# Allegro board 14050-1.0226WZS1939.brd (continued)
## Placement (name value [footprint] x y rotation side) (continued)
C1980  SC1KP50V2KX-1DLGP  [C402H22]  151.29 150.88 0 bottom
C1981  SC1KP50V2KX-1DLGP  [C402H22]  145.45 191.9 180 bottom
C1982  SCD1U16V2KX-3DLGP  [C402H22]  146.34 191.9 180 bottom
C3131  SC100P3KV8JN-4-GP  [C1808H87]  64.04 19.56 0 bottom
C3366  SCD1U16V2KX-3DLGP  [C402H22]  127.92 41.53 180 top
C3367  SC10U10V5KX-2DLGP  [C805H50]  134.27 51.31 0 bottom
C3368  SCD1U16V2KX-3DLGP  [C402H22]  138.33 32.46 270 top
C3369  SCD1U16V2KX-3DLGP  [C402H22]  138.33 36.01 270 top
C3370  SCD1U16V2KX-3DLGP  [C402H22]  138.33 34.24 270 top
C3371  SCD1U16V2KX-3DLGP  [C402H22]  138.33 33.35 270 top
C3372  SCD1U16V2KX-3DLGP  [C402H22]  138.33 35.13 270 top
C3373  SCD1U16V2KX-3DLGP  [C402H22]  138.33 36.9 270 top
C3374  SCD1U16V2KX-3DLGP  [C402H22]  138.33 38.68 270 top
C3375  SCD1U16V2KX-3DLGP  [C402H22]  138.33 37.79 270 top
C3376  SCD01U50V2KX-1DLGP  [C402H22]  136.93 29.59 180 top
C3377  SCD1U16V2KX-3DLGP  [C402H22]  128.8 29.6 0 top
C3378  SCD1U16V2KX-3DLGP  [C402H22]  129.69 41.54 180 top
C3379  SCD1U16V2KX-3DLGP  [C402H22]  136.68 41.54 180 top
C3380  SCD01U50V2KX-1DLGP  [C402H22]  133.88 29.6 0 top
C3381  SCD01U50V2KX-1DLGP  [C402H22]  135.8 41.48 0 top
C3382  SCD1U16V2KX-3DLGP  [C402H22]  135.8 41.48 0 bottom
C3383  SCD1U16V2KX-3DLGP  [C402H22]  128.81 41.53 180 top
C3452  SCD01U50V2KX-1DLGP  [C402H22]  49.82 17.78 180 top
C3453  SCD1U16V2KX-3DLGP  [C402H22]  39.02 12.83 0 bottom
C3454  SCD1U16V2KX-3DLGP  [C402H22]  38.51 20.07 180 top
C3455  SCD1U25V2KX-1-DL-GP  [C402H22]  36.69 32.03 0 top
C3456  SCD1U25V2KX-LL-GP  [C402H22]  39.15 34.92 180 top
C3457  SCD01U50V2KX-1DLGP  [C402H22]  40.95 35.86 270 top
C3458  SCD01U50V2KX-1DLGP  [C402H22]  40.8 38.1 270 top
C3459  SC10U25V5KX-DL-GP  [C805H58]  49.94 43.05 90 top
C3460  SC10U25V5KX-DL-GP  [C805H58]  49.94 45.09 90 top
C4101  SC1U10V2KX-1DLGP  [C402H22]  94.52 52.2 180 bottom
C4102  SC1U10V2KX-1DLGP  [C402H22]  107.48 55.63 180 top
C6701  SCD1U16V2KX-3DLGP  [C402H22]  81.92 68.83 180 top
C6702  SCD1U16V2KX-3DLGP  [C402H22]  81.92 70.76 0 top
C6703  SC10U6D3V3MX-GP  [C603H38]  75.09 69.62 270 top
C6704  SCD01U50V2KX-1DLGP  [C402H22]  99.09 119.63 180 top
C6705  SC10U10V5KX-2GP  [C805H54]  93.25 117.47 270 top
C6706  SC10U10V5KX-2DLGP  [C805H50]  96.93 117.47 90 top
C6707  SCD1U10V2KX-4GP  [C402H20]  99.09 123.7 0 top
C6708  SCD1U16V2KX-3DLGP  [C402H22]  93.38 114.05 270 top
C6709  SCD1U16V2KX-3DLGP  [C402H22]  96.93 119 90 top
C6710  SC10U6D3V3MX-DL-GP  [C603H36]  48.42 117.73 270 top
C6711  SCD1U16V2KX-3DLGP  [C402H22]  48.67 104.01 270 top
C6712  SCD22U10V2KX-2-GP  [C402H22]  160.43 209.68 180 bottom
C6714  SC10U6D3V3MX-DL-GP  [C603H36]  159.29 209.55 180 bottom
C6715  SC10U6D3V3MX-DL-GP  [C603H36]  159.29 215.39 0 bottom
C6716  SC1U10V2KX-1GP  [C402H22]  90.97 118.49 0 top
C6717  SCD1U16V2KX-3DLGP  [C402H22]  48.29 80.01 270 top
C6718  SCD1U25V3KX-DLGP  [C603H36]  65.79 46.13 270 top
C6719  SCD1U25V3KX-DLGP  [C603H36]  69.27 29.69 180 top
C6720  SCD1U25V3KX-DLGP  [C603H36]  36.61 52.45 90 bottom
C6721  SCD1U16V2KX-3DLGP  [C402H22]  128.81 27.18 180 top
C6722  SC100P50V2JN-3DLGP  [C402H22]  32.8 20.95 0 top
C6723  SCD1U10V2KX-4GP  [C402H20]  111.67 92.96 180 bottom
C6724  SCD01U25V2KX-3DLGP  [C402H22]  83.6 58.29 180 bottom
C6725  SCD1U10V2KX-4GP  [C402H20]  88.93 54.23 270 bottom
C6726  SC4D7P50V2CN-1-DL-GP  [C402H22]  93.53 36.96 0 top
C6727  SC4D7P50V2CN-1-DL-GP  [C402H22]  92.11 36.96 0 top
C6728  SC4D7P50V2CN-1-DL-GP  [C402H22]  94.39 36.96 0 top
C6729  SC4D7P50V2CN-1-DL-GP  [C402H22]  95.84 36.96 0 top
CONVT1  CLX-CON10-10-GP  [CI1410M1HRL-NH]  25 36.65 270 top
CPU1  CARRIZO-L-GP  [BGA968M2937H74]  83 165 0 top
D1  1SS355-4-GP  [SOD323AKH38]  14.26 218.69 180 top
D4  IP4223CZ6-1-GP  [SOT-6H44]  168.25 107.6 270 top
D7  BAT54A-12-GP  [SOT23-2D4-312H44]  105.57 92.2 180 top
D16  P6SMB27A-1-GP  [DO214AAAK-1121H97]  62.52 26.67 180 top
D19  BAV99GP-GP  [SOT23-2D4-312H48]  62.72 36.4 180 bottom
D20  BAT54A-12-GP  [SOT23-2D4-312H44]  60.23 146.18 180 top
D21  AZ2015-01H-GP  [SOD523AKH28]  164.37 88.06 0 bottom
D23  BAT54C-11-GP  [SOT23-2D4-312H44]  73.06 49.07 90 top
D24  IP4223CZ6-1-GP  [SOT-6H44]  93.97 29.97 180 top
D31  1SS355-4-GP  [SOD323AKH38]  131.61 25.91 270 top
D32  BX310F-R1-00000-GP  [D4724AKH44]  37.75 41.58 270 top
D33  CH551H-30PT-GP  [SOD80CH36]  73.31 46.15 270 top
D34  BAT54A-12-GP  [SOT23-2D4-312H44]  103.67 105.54 0 top
DCIN1  DC-JACK345-GP  [2DC3115-000111F]  53.25 25.53 270 top
DCIN2  ACES-CONN14G-GP  [88314-077N]  55.64 33.67 180 top
DIMM1  DDR3-204P-262-GP-U  [AS0A621-J4R6-7H-U]  135.3 158.9 90 top
DIMM2  DDR3-204P-142-GP-U  [AS0A626-J8R6-7H]  150.5 158.9 90 top
F1  POLYSW-1D5A6V-12-GP  [POLYSW-2114H30]  160.31 194.56 180 bottom
F2  POLYSW-2A6V-7-GP  [POLYSW-2114H30]  39.53 107.44 270 bottom
F3  POLYSW-1D5A6V-12-GP  [POLYSW-2114H30]  161.75 190.53 90 bottom
F5  POLYSW-2A6V-7-GP  [POLYSW-2114H30]  6.13 210.44 0 bottom
F6  POLYSW-1D5A6V-12-GP  [POLYSW-2114H30]  161.7 142.75 0 top
F12  POLYSW-2A6V-7-GP  [POLYSW-2114H30]  105.82 18.67 180 top
F13  POLYSW-1D5A6V-12-GP  [POLYSW-2114H30]  107.09 32.77 270 top
F14  POLYSW-2A6V-7-GP  [POLYSW-2114H30]  169.07 124.71 90 top
F15  POLYSW-1D5A6V-12-GP  [POLYSW-2114H30]  24.29 6.22 270 bottom
F16  FUSE-3A32V-26-GP  [FUSE-1608H22]  50.58 49.07 270 top
FANC3  FOX-CON4-30-GP  [HF1804H]  14 211 270 top
G5  COPPER-CLOSE-GP-U  [CON2C-U]  141.77 36.83 180 top
GPU1  SUN-S3-XT-GP  [BGA631M23H82]  83 100 90 top
H1  HOLE237R158-GP  [HOLE237R158]  94.38 192.31 180 top
H2  HOLE237R158-GP  [HOLE237R158]  62.39 165.12 180 top
H3  HOLE237R158-GP  [HOLE237R158]  94.38 137.93 180 top
H4  HOLE237R158-GP  [HOLE237R158]  69 123.75 180 top
H5  HOLE237R158-GP  [HOLE237R158]  94.39 76.25 180 top
H6  GEN8D5X8R5X4D5-8-F-A-GP  [GEN8D5X8R5X4D5-8-F-A]  165 225 270 top
H7  GEN315R138-8-F-A-1-GP  [GEN315R138-8-F-A-1]  5 160 180 top
H9  GEN8D5X8R5X4D5-8-F-A-GP  [GEN8D5X8R5X4D5-8-F-A]  25 49.15 180 top
H10  GEN315R178-8-F-A-3-GP  [GEN315R178-8-F-A-1]  165 20 180 top
H11  GEN315R138-8-F-A-1-GP  [GEN315R138-8-F-A-1]  172.5 64.43 180 top
HDD1  SKT-SATA7P-184-GP-U  [15-02070-5A61-A]  12 142 270 top
HDMI1  SKT-HDMI22-12-GP  [SKT-HDMI22-150077]  113.99 37.03 270 top
HDMI2  ARG-CON20-GP  [LVDFH-02004-TP00]  118.69 37.07 270 top
HDT1  SMC-CONN20A-1-GP  [ASP-137098-05]  94.78 213.74 90 top
HS6  STF256R109H99-GP  [STF256R109H99]  144.25 214 180 top
L1  HCB2012KF-600T30-GP  [L20125H42]  35.97 107.44 270 bottom
L2  IND-2D2UH-250-GP-U  [L3030-2709H41]  31.83 104.65 0 bottom
L4  FILTER-4P-123-GP  [L125100-4P-1H36]  165.64 117.98 180 top
L5  FILTER-4P-123-GP  [L125100-4P-1H36]  165.64 115.7 180 top
L10  MHC1608S221NBP-GP  [L603H38]  153.2 37.08 90 top
L15  BLM15BD102SN1D-GP  [L402H22]  55.48 35.25 180 bottom
L16  HCB1608KF-800T30-GP  [L603H38]  39.99 105.71 270 bottom
L17  HCB1608KF-800T30-GP  [L603H38]  32.72 78.26 270 bottom
L19  HCB1608KF-800T30-GP  [L603H38]  165.64 88.27 180 bottom
L20  MCB1005S121FBP-GP  [L402H24]  82.58 38.1 180 top
L21  MCB1005S121FBP-GP  [L402H24]  158.86 74.85 0 bottom
L31  HCB2012KF-601T20-GP  [L20125H42]  142.53 20.83 0 top
L32  HCB2012KF-601T20-GP  [L20125H42]  144.69 20.83 0 top
L33  HCB2012KF-601T20-GP  [L20125H42]  150.15 20.83 0 top
L34  HCB2012KF-601T20-GP  [L20125H42]  147.99 20.83 0 top
L46  -  [0R0805-PAD]  107.09 34.92 270 top
L47  MCB1005S121FBP-GP  [L402H24]  96.3 99.57 180 bottom
L48  MCB1005S121FBP-GP  [L402H24]  93.4 105.14 90 bottom
L49  MCB1005S121FBP-GP  [L402H24]  74.61 81.89 180 top
L50  MCB1005S121FBP-GP  [L402H24]  79.43 87.61 90 bottom
L51  MCB1005S121FBP-GP  [L402H24]  73.34 81.89 180 top
L52  MHC1608S221NBP-GP  [L603H38]  92 94.21 0 bottom
L53  MHC1608S221NBP-GP  [L603H38]  89.08 91.04 270 bottom
L54  MCB1005S121FBP-GP  [L402H24]  157.51 84.71 270 top
L55  FCM1608KF-2-GP-U  [L1608-UH38]  107.6 19.05 180 top
L56  FILTER-4P-123-GP  [L125100-4P-1H36]  165.64 96.52 180 top
L57  FILTER-4P-123-GP  [L125100-4P-1H36]  165.64 94.23 180 top
L60  MHC1608S181NBP-GP  [L603H38]  141.77 39.75 90 top
L61  IND-33UH-83-GP  [L8080-6522-1H166]  43.01 47.8 270 top
L62  MCB1005S121FBP-GP  [L402H24]  84.74 37.21 180 top
L4101  BLM15HG102SN1D-GP  [L402H22]  106.08 54.86 180 top
L4102  FILTER-4P-123-GP  [L125100-4P-1H36]  18.83 140.84 0 top
L4103  FILTER-4P-123-GP  [L125100-4P-1H36]  18.83 143 0 top
LED2  LED-O-23-GP  [LED1608AKH30]  95.16 7.24 180 top
LED3  LED-O-23-GP  [LED1608AKH30]  168.05 128.91 90 top
LOUT1  AUDIO-JK419-GP  [JAC331-0140A8B-9H]  76.93 37.66 90 top
LPC1  FOX-CONN14A-S1-GP  [HL5507F]  120.28 55.09 0 top
LVDS1  ACES-CON30-21-GP  [50524-0300N-001]  36.8 95 270 top
MEM1  H5TQ1G63DFR-11C-1-GP  [BGA96D075130H48]  55.61 111.68 0 top
MEM2  H5TQ1G63DFR-11C-1-GP  [BGA96D075130H48]  55.61 91.62 180 top
MEM3  H5TQ1G63DFR-11C-1-GP  [BGA96D075130H48]  55.61 111.68 180 bottom
MEM4  H5TQ1G63DFR-11C-1-GP  [BGA96D075130H48]  55.61 91.62 0 bottom
MEMCD1  SKT-SDCARD-52-GP  [156-5101902601]  174.65 144.79 90 top
NGFF1  SKT-MINI67P-3-GP-U1  [2199230-7]  116 214 270 top
NOREF  -  []  -10 0 0 top
NOREF#2  -  [unnamed#2]  6.64 9.4 0 top
NOREF#3  *  [unnamed#2]  62.77 66.55 0 top
NOREF#4  *  [unnamed#2]  72.55 202.69 0 top
NOREF#5  -  []  152.81 98.04 0 top
NOREF#6  *  [unnamed#2]  171.63 8.45 0 top
NOREF#7  *  [unnamed#2]  7.78 219.33 0 top
NOREF#8  -  []  -10 0 0 top
NOREF#9  -  []  105.19 194.31 0 top
NOREF#10  -  []  -10 0 0 top
NOREF#11  -  [unnamed#2]  178.22 223.03 0 top
NOREF#12  *  [unnamed#2]  157.46 223.44 0 top
NOREF#13  -  []  -10 0 0 top
NOREF#14  -  []  133.89 208.03 0 top
NOREF#15  -  [unnamed#2]  6.64 225.3 0 top
NOREF#16  -  []  0 103.25 0 top
NOREF#17  *  [unnamed#2]  178.33 217.98 0 top
NOREF#18  -  [unnamed#2]  184.44 225.3 0 top
NOREF#19  -  []  113.73 178.94 0 top
NOREF#20  *  [unnamed#2]  166.66 27.56 0 top
NOREF#21  -  [unnamed#2]  171.63 4.95 0 top
NOREF#22  -  []  -310 0 0 top
NOREF#23  -  [unnamed#2]  11.57 4.95 0 top
NOREF#24  -  [unnamed#2]  149 223.77 0 top
NOREF#25  *  [unnamed#2]  101.76 136.14 0 top
NOREF#26  *  [unnamed#2]  40.67 23.11 0 top
NOREF#27  *  [unnamed#2]  5.05 6.01 0 top
NOREF#28  *  [unnamed#2]  171.63 8.45 180 bottom
NOREF#29  -  []  178.7 28.65 90 bottom
NOREF#30  *  [unnamed#2]  49.56 123.7 180 bottom
NOREF#31  *  [unnamed#2]  40.17 24.64 180 bottom
NOREF#32  *  [unnamed#2]  157.46 223.44 180 bottom
NOREF#33  *  [unnamed#2]  45.37 223.77 180 bottom
NOREF#34  -  []  120.05 156.34 90 bottom
NOREF#35  *  [unnamed#2]  178.33 217.98 180 bottom
NOREF#36  *  [unnamed#2]  5.05 6.01 180 bottom
ODD1  SKT-SATA7P-184-GP-U  [15-02070-5A61-A]  8.4 177 270 top
PC1  SC1U10V2KX-1DLGP  [C402H22]  124.87 208.41 90 bottom
PC4  SC22P50V2JN-4DLGP  [C402H22]  121.95 71.09 90 bottom
PC5  SCD22U25V3KX-GP  [C603H40]  122.31 72.87 180 bottom
PC6  SC150P50V2JN-3DLGP  [C402H22]  119.54 65.02 0 top
PC7  SC1KP50V2KX-1DLGP  [C402H22]  119.03 66.42 90 top
PC8  SC33P50V2JN-3DLGP  [C402H22]  120.94 66.42 90 top
PC9  SCD01U50V2KX-1GP  [C402H22]  120.18 72.52 0 bottom
PC11  SC390P50V2KX-1-GP  [C402H22]  128.81 71.25 180 top
PC12  SC2D2U10V3KX-1DLGP-U  [C603H36]  111.79 71.5 270 top
PC13  SC330P50V2KX-3-DL-GP  [C402H22]  126.91 73.28 180 top
PC14  SCD01U50V2KX-1GP  [C402H22]  127.54 74.93 90 top
PC15  SCD033U25V2KX-1-GP  [C402H22]  130.46 75.31 180 bottom
PC16  SCD22U25V3KX-DL-GP  [C603H36]  129.19 75.69 180 bottom
PC17  SC1U16V3KX-4DLGP  [C603H36]  119.67 80.64 180 top
PC18  SC1U16V3KX-4DLGP  [C603H36]  118.4 80.64 180 top
PC19  SCD22U25V3KX-DL-GP  [C603H36]  122.33 80.64 180 top
PC20  SCD1U50V3KX-DL-GP  [C603H35]  124.37 71.88 270 bottom
PC24  SC10U25V6KX-4DL-GP  [C1206H71]  120.94 87.25 90 bottom
PC34  SCD1U10V2KX-5GP  [C402H22]  101.25 64.64 90 bottom
PC48  SCD1U10V2KX-5GP  [C402H22]  17.43 157.35 270 bottom
PC49  SC1U16V3KX-4DLGP  [C603H36]  164.5 207.9 90 top
PC50  SC10U6D3V5KX-4DLGP-U  [C805H58]  154.21 207.52 270 top
PC51  SCD1U50V3KX-DL-GP  [C603H35]  152.69 205.87 90 top
PC52  SC10U6D3V5KX-4DLGP-U  [C805H58]  158.91 207.14 270 top
PC56  SC330P50V2KX-3-DL-GP  [C402H22]  123.86 72.9 90 bottom
PC57  SC1KP50V2KX-1DLGP  [C402H22]  123.86 73.79 270 bottom
PC58  SC1U16V3KX-4DLGP  [C603H36]  123.1 75.56 90 bottom
PC59  SCD1U16V3KX-3GP  [C603H36]  127.92 77.22 270 top
PC60  SCD22U25V3KX-DL-GP  [C603H36]  123.1 76.83 90 bottom
PC61  SC10U25V6KX-4DL-GP  [C1206H71]  120.94 89.41 270 top
PC62  SCD1U50V3KX-DL-GP  [C603H35]  120.94 91.19 270 top
PC63  SC10U25V6KX-4DL-GP  [C1206H71]  120.94 87.12 270 top
PC64  SC10U25V6KX-4DL-GP  [C1206H71]  120.94 89.53 90 bottom
PC65  SC1500P50V3KX-DLGP  [C603H36]  121.32 94.49 0 top
PC68  SC27P50V2JN-2DLGP  [C402H22]  66.2 80.77 90 top
PC73  SCD01U50V2KX-1DLGP  [C402H22]  86.01 94.36 270 bottom
PC96  SCD1U16V2KX-3DLGP  [C402H22]  105.95 6.99 0 top
PC126  SC22P50V2JN-4GP  [C402H22]  157.26 194.31 90 top
PC140  SC1U10V2KX-1DLGP  [C402H22]  39.66 8 0 bottom
PC151  SCD1U16V2KX-3DLGP  [C402H22]  72.42 78.36 90 top
PC2127  SC470P50V2KX-3DLGP  [C402H22]  152.81 17.02 270 top
PC4301  SC10P50V2JN-4DLGP  [C402H22]  35.21 64.39 90 top
PC4302  SCD1U50V3KX-DL-GP  [C603H35]  36.48 71.63 180 top
PC4303  SC2200P50V2KX-2DLGP  [C402H22]  36.48 71.5 0 bottom
PC4304  SC470P50V2KX-3DLGP  [C402H22]  35.21 61.34 90 top
PC4305  SC10P50V2JN-4DLGP  [C402H22]  35.21 65.28 90 top
PC4401  SC10U25V5KX-DL-GP  [C805H58]  34.86 71.27 0 bottom
PC4402  SCD1U50V3KX-DL-GP  [C603H35]  57.69 61.34 270 bottom
PC4403  SCD1U50V3KX-DL-GP  [C603H35]  59.09 62.61 270 bottom
PC4404  SCD1U50V3KX-DL-GP  [C603H35]  56.29 62.61 90 bottom
PC4405  SCD1U25V2KX-1-DL-GP  [C402H22]  42.63 54.79 90 top
PC4406  SC10U25V5KX-DL-GP  [C805H58]  43.21 53.34 270 bottom
PC4407  SC10U25V5KX-DL-GP  [C805H58]  43.21 53.34 90 top
PC4408  SC1U25V5KX-3-GP  [C805H58]  55.53 58.93 90 bottom
PC4426  SC1U25V3KX-1-GP  [C603H36]  73.06 53.72 90 bottom
PC4601  SC1KP50V2KX-1DLGP  [C402H22]  24.29 222.63 270 bottom
PC4602  SC1U25V3KX-1-DLGP  [C603H36]  32.01 220.47 0 top
PC4603  SC3300P50V2KX-1DLGP  [C402H22]  22.64 217.17 180 bottom
PC4605  SC1KP50V2KX-1DLGP  [C402H22]  34.96 224.03 0 bottom
PC4606  SC1KP50V2KX-1DLGP  [C402H22]  27.34 216.92 90 top
PC4607  SCD1U16V2KX-3DLGP  [C402H22]  26.83 224.03 180 bottom
PC4608  SC2D2U10V3KX-1DLGP-U  [C603H36]  31.4 215.52 180 top
PC4609  SCD01U50V2KX-1DLGP  [C402H22]  27.34 217.81 270 top
PC4610  SC330P50V2KX-3-DL-GP  [C402H22]  38.51 221.62 90 bottom
PC4611  SC2200P50V2KX-2DLGP  [C402H22]  38.51 219.58 90 bottom
PC4612  SC10P50V2JN-4DLGP  [C402H22]  36.99 220.09 180 bottom
PC4613  SC330P50V2KX-3-DL-GP  [C402H22]  37.5 215.52 90 bottom
PC4614  SCD01U50V2KX-1DLGP  [C402H22]  33.05 220.73 0 top
PC4615  SC680P50V2KX-2DLGP  [C402H22]  23.15 214.63 90 bottom
PC4616  SCD01U50V2KX-1DLGP  [C402H22]  33.05 218.69 270 top
PC4617  SC680P50V2KX-2DLGP  [C402H22]  37.5 214.63 270 bottom
PC4618  SC1KP50V2KX-1DLGP  [C402H22]  23.15 213.74 270 bottom
PC4619  SCD1U16V2KX-3DLGP  [C402H22]  35.97 220.73 180 top
PC4621  SC330P50V2KX-3-DL-GP  [C402H22]  21.75 221.11 180 bottom
PC4622  SC1KP50V2KX-1DLGP  [C402H22]  33.05 216.03 270 top
PC4623  SCD047U16V2KX-1-DL-GP  [C402H22]  37.5 214.63 90 top
PC4624  SC3300P50V2KX-1DLGP  [C402H22]  38.01 218.06 180 bottom
PC4626  SC2200P50V2KX-2DLGP  [C402H22]  22.26 218.57 270 bottom
PC4627  SC10P50V2JN-4DLGP  [C402H22]  23.66 219.07 180 bottom
PC4628  SCD047U16V2KX-1-DL-GP  [C402H22]  23.15 213.74 90 top
PC4701  SC10U25V6KX-4DL-GP  [C1206H71]  41.56 199.01 90 bottom
PC4702  SC10U25V6KX-4DL-GP  [C1206H71]  41.56 201.29 270 top
PC4703  SCD1U50V3KX-DL-GP  [C603H35]  41.44 199.52 270 top
PC4704  SCD22U25V3KX-DL-GP  [C603H36]  32.93 209.42 0 bottom
PC4705  SC10U25V6KX-4DL-GP  [C1206H71]  41.56 201.29 90 bottom
PC4706  SC1KP50V2KX-1DLGP  [C402H22]  42.45 195.2 180 top
PC4707  SC10U25V6KX-4DL-GP  [C1206H71]  27.85 201.19 270 bottom
PC4708  SC10U25V6KX-4DL-GP  [C1206H71]  27.85 201.17 90 top
PC4709  SCD1U50V3KX-DL-GP  [C603H35]  27.85 199.39 90 top
PC4710  SCD22U25V3KX-DL-GP  [C603H36]  28.74 209.42 0 bottom
PC4711  SC10U25V6KX-4DL-GP  [C1206H71]  27.85 199.01 270 bottom
PC4712  SC1KP50V2KX-1DLGP  [C402H22]  27.08 195.2 180 top
PC4713  SCD1U50V3KX-DL-GP  [C603H35]  29.75 164.59 90 top
PC4801  SC10U25V6KX-4DL-GP  [C1206H71]  26.07 157.86 0 top
PC4802  SCD1U16V2KX-3DLGP  [C402H22]  40.67 152.02 270 top
PC4803  SC1U10V2KX-1DLGP  [C402H22]  23.07 155.68 90 top
PC4804  SC1KP50V2KX-1DLGP  [C402H22]  17.43 156.46 270 bottom
PC4805  SC18P50V2JN-1DLGP  [C402H22]  13.62 154.18 180 top
PC4806  SCD1U50V3KX-DL-GP  [C603H35]  24.29 158.12 180 top
PC4807  SC1KP50V2KX-1DLGP  [C402H22]  33.18 156.84 270 top
PC4808  SC10U25V6KX-4DL-GP  [C1206H71]  26.07 157.86 180 bottom
PC4901  SCD01U50V2KX-1DLGP  [C402H22]  123.22 8.97 90 bottom
PC4902  SC10U25V6KX-4DL-GP  [C1206H71]  121.11 7.11 0 bottom
PC4903  SCD1U50V3KX-DL-GP  [C603H35]  115.6 10.16 180 top
PC4904  SC10U25V6KX-4DL-GP  [C1206H71]  120.48 23.24 180 bottom
PC4905  SCD01U50V2KX-1DLGP  [C402H22]  123.3 21.11 90 bottom
PC4906  SC1U10V2KX-1DLGP  [C402H22]  114.84 13.97 90 top
PC4907  SCD1U50V3KX-DL-GP  [C603H35]  112.05 6.22 0 top
PC4908  SCD1U50V3KX-DL-GP  [C603H35]  112.56 17.14 0 top
PC4909  SC1U10V2KX-1DLGP  [C402H22]  132.62 5.97 0 top
PC4910  SC1U10V2KX-1DLGP  [C402H22]  132.62 22.99 180 top
PC4911  SC22P50V2JN-4DLGP  [C402H22]  106.97 10.03 0 top
PC4912  SC1U16V3KX-4DLGP  [C603H36]  106.08 15.75 270 top
PC4913  SC22P50V2JN-4DLGP  [C402H22]  106.97 14.1 0 top
PC4914  SC4D7U6D3V3KX-DLGP  [C603H36]  115.22 14.99 270 top
PC4915  SC1500P50V3KX-DLGP  [C603H36]  122.92 20.09 90 bottom
PC4916  SC1500P50V3KX-DLGP  [C603H36]  122.84 10.01 90 bottom
PC4917  SC18P50V2JN-1DLGP  [C402H22]  106.46 14.1 90 bottom
PC4918  SC18P50V2JN-1DLGP  [C402H22]  106.46 10.03 90 bottom
PC5001  SC10U10V5KX-2DLGP  [C805H50]  136.05 80.77 270 top
PC5003  SC1KP50V2KX-1DLGP  [C402H22]  147.1 80.39 270 top
PC5009  SC1U10V2KX-1DLGP  [C402H22]  146.46 76.96 90 top
PC5010  SCD1U50V3KX-DL-GP  [C603H35]  144.31 83.57 0 top
PC5011  SC10U10V5KX-2DLGP  [C805H50]  137.32 83.95 180 top
PC5012  SC1U16V3KX-4DLGP  [C603H36]  143.29 104.01 0 top
PC5013  SC18P50V2JN-1DLGP  [C402H22]  139.99 74.04 90 top
PC5014  SCD033U25V3KX-DL-GP  [C603H36]  136.43 75.11 270 top
PC5016  SC10U10V5KX-2DLGP  [C805H50]  135.29 83.95 180 top
PC5017  SC1500P50V3KX-DLGP  [C603H36]  141.38 93.27 180 bottom
PC5018  SC1U10V2KX-1DLGP  [C402H22]  146.46 76.07 90 top
PC5019  SCD1U50V3KX-DL-GP  [C603H35]  138.84 92.58 270 bottom
PC5020  SC10U25V6KX-4DL-GP  [C1206H71]  138.84 88.52 270 bottom
PC5021  SC10U25V6KX-4DL-GP  [C1206H71]  138.84 90.81 270 bottom
PC5022  SC10U25V6KX-4DL-GP  [C1206H71]  138.84 88.52 90 top
PC5202  SC1500P50V3KX-DLGP  [C603H36]  107.22 66.8 270 bottom
PC5203  SC22P50V2JN-4DLGP  [C402H22]  101.25 61.59 90 top
PC5204  SC1U10V2KX-1DLGP  [C402H22]  101.25 64.64 270 top
PC5205  SC22U6D3V3MX-1-DL-GP  [C603H40]  103.03 77.34 180 top
PC5209  SC10U25V6KX-4DL-GP  [C1206H71]  106.97 58.55 90 top
PC5210  SC22U6D3V3MX-1-DL-GP  [C603H40]  104.3 77.34 180 top
PC5211  SC22U6D3V3MX-1-DL-GP  [C603H40]  105.57 77.34 180 top
PC5212  SC22U6D3V3MX-1-DL-GP  [C603H40]  101.76 77.34 180 top
PC5213  SCD1U16V2KX-3DLGP  [C402H22]  100.62 77.34 180 top
PC5214  SC10U25V6KX-4DL-GP  [C1206H71]  106.97 60.83 90 top
PC5217  SCD1U25V2KX-1-DL-GP  [C402H22]  101.25 66.67 90 top
PC5232  SCD01U50V2KX-1DLGP  [C402H22]  65.44 57.53 270 bottom
PC5233  SC1U10V2KX-1DLGP  [C402H22]  55.63 53.34 0 bottom
PC5234  SCD1U50V3KX-DL-GP  [C603H35]  55.91 57.23 270 bottom
PC5235  SC1KP50V2KX-1DLGP  [C402H22]  44.94 70.15 180 top
PC5236  SCD1U50V3KX-DL-GP  [C603H35]  60.99 49.78 270 bottom
PC5237  SC470P50V2KX-3DLGP  [C402H22]  58.86 51.99 180 bottom
PC5238  SCD1U25V2KX-1-DL-GP  [C402H22]  62.77 49.28 180 bottom
PC5239  SC220P50V2KX-3DLGP  [C402H22]  65.44 56.52 270 bottom
PC5240  SC10U25V5KX-DL-GP  [C805H58]  34.86 71.27 180 top
PC5241  SC10U25V5KX-DL-GP  [C805H58]  38.13 64.14 0 top
PC5242  SCD1U50V3KX-DL-GP  [C603H35]  39.78 64.26 0 top
PC5243  SC1U16V3KX-4DLGP  [C603H36]  18.96 147.83 270 top
PC5244  SC100P50V2JN-3DLGP  [C402H22]  31.28 143.26 0 top
PC5245  SCD1U10V2KX-5GP  [C402H22]  22 138.68 0 top
PC5246  SC1U16V3KX-4DLGP  [C603H36]  32.42 146.81 180 top
PC5247  SC10U10V5KX-2DLGP  [C805H50]  24.93 148.72 180 top
PC5248  SC10U10V5KX-2DLGP  [C805H50]  30.77 146.69 180 top
PC5401  SC10U25V6KX-4DL-GP  [C1206H71]  49.31 214.88 90 top
PC5402  SC10U25V6KX-4DL-GP  [C1206H71]  49.31 217.42 90 top
PC5403  SCD1U50V3KX-DL-GP  [C603H35]  49.94 216.03 270 bottom
PC5404  SC10U25V6KX-4DL-GP  [C1206H71]  42.22 212.57 270 top
PC5405  SC1KP50V2KX-1DLGP  [C402H22]  52.99 221.11 0 bottom
PC5411  SCD22U25V3KX-DL-GP  [C603H36]  71.66 213.74 270 bottom
PC5413  SC1KP50V2KX-1DLGP  [C402H22]  77.5 218.69 0 top
PC5414  SC1KP50V2KX-1DLGP  [C402H22]  75.09 222.88 180 bottom
PC5415  SC330P50V2KX-3-DL-GP  [C402H22]  82.84 223.9 180 bottom
PC5416  SC10P50V2JN-4DLGP  [C402H22]  81.95 222.88 180 bottom
PC5417  SC2200P50V2KX-2DLGP  [C402H22]  81.06 222.88 180 bottom
PC5418  SC1KP50V2KX-1DLGP  [C402H22]  84.74 219.2 180 bottom
PC5419  SC3300P50V2KX-1DLGP  [C402H22]  79.66 222.38 90 bottom
PC5420  SC1U25V3KX-1-DLGP  [C603H36]  85.63 214.38 270 bottom
PC5421  SC2D2U16V3KX-DL-GP  [C603H36]  76.49 209.17 180 bottom
PC5422  SCD1U10V2KX-5DLGP  [C402H22]  81.57 218.69 180 top
PC5423  SCD01U25V2KX-3DLGP  [C402H22]  79.54 218.69 180 top
PC5424  SCD01U25V2KX-3DLGP  [C402H22]  82.71 209.55 180 bottom
PC5425  SC680P50V2KX-2DLGP  [C402H22]  74.2 222.88 0 bottom
PC5426  SCD047U16V2KX-1-DL-GP  [C402H22]  71.66 221.49 270 bottom
PC5427  SC1U16V3KX-4DLGP  [C603H36]  154.97 208.79 270 bottom
PC5428  SC1U16V3KX-4DLGP  [C603H36]  154.97 213.11 270 bottom
PC5429  SC1U16V3KX-4DLGP  [C603H36]  151.04 212.85 90 bottom
PC5430  SC10U10V5KX-2DLGP  [C805H50]  48.04 84.12 270 top
PC5431  SC10U10V5KX-2DLGP  [C805H50]  77.25 76.33 180 top
PC5432  SC10U10V5KX-2DLGP  [C805H50]  75.22 76.33 180 top
PC5433  SCD1U16V2KX-3DLGP  [C402H22]  68.74 81.28 180 top
PC5434  SC10U10V5KX-2DLGP  [C805H50]  48.04 82.17 270 top
PC5435  SC1U25V3KX-1-DLGP  [C603H36]  72.8 77.22 90 top
PD4401  RB520SM-30T2R-GP  [D1608-035030AKH28]  54.24 54.48 0 bottom
PD4405  1N4148WS-7-F-GP  [SOD323AKH42]  72.8 63.75 270 bottom
PG3  GAP-CLOSE  [CON2C]  118.91 110.62 180 top
PG4  GAP-CLOSE  [CON2C]  118.91 104.39 0 top
PG4701  COPPER-CLOSE-GP-U  [CON2C-U]  40.29 185.17 0 top
PG4702  COPPER-CLOSE-GP-U  [CON2C-U]  40.29 178.82 180 top
PG4703  COPPER-CLOSE-GP-U  [CON2C-U]  29.12 185.17 0 top
PG4704  COPPER-CLOSE-GP-U  [CON2C-U]  29.12 178.82 180 top
PG4801  GAP-CLOSE-PWR-3-GP  [GAP-CLOSE-PWR-3]  40.67 151 0 top
PG4901  GAP-CLOSE-PWR-3-GP  [GAP-CLOSE-PWR-3]  115.1 13.08 0 top
PG4902  GAP-CLOSE-PWR-3-GP  [GAP-CLOSE-PWR-3]  136.94 5.08 90 top
PG4903  GAP-CLOSE-PWR-3-GP  [GAP-CLOSE-PWR-3]  136.94 24.26 90 top
PG4904  GAP-CLOSE-PWR-3-GP  [GAP-CLOSE-PWR-3]  114.71 16.13 0 top
PG4905  GAP-CLOSE-PWR-3-GP  [GAP-CLOSE-PWR-3]  58.58 48.26 0 top
PG4906  GAP-CLOSE-PWR-3-GP  [GAP-CLOSE-PWR-3]  47.66 65.79 270 bottom
PG4907  GAP-CLOSE-PWR-3-GP  [GAP-CLOSE-PWR-3]  58.58 47.32 0 top
PG4908  GAP-CLOSE-PWR-3-GP  [GAP-CLOSE-PWR-3]  49.18 65.79 270 bottom
PG5001  GAP-CLOSE-PWR-3-GP  [GAP-CLOSE-PWR-3]  134.15 107.7 270 top
PG5205  -  [GAP-CLOSE-PWR]  103.92 58.67 0 top
PG5210  -  [GAP-CLOSE-PWR]  103.92 57.91 0 top
PG5211  GAP-CLOSE-PWR-3-GP  [GAP-CLOSE-PWR-3]  99.35 76.58 180 top
PG5212  GAP-CLOSE-PWR-3-GP  [GAP-CLOSE-PWR-3]  106.97 76.58 0 top
PG5401  COPPER-CLOSE-GP-U  [CON2C-U]  59.22 211.46 0 top
PG5402  COPPER-CLOSE-GP-U  [CON2C-U]  59.22 205.1 180 top
PL1  IND-D36UH-19-GP  [L115100-2H158]  118.91 107.44 180 top
PL4301  MLVS0402M04-GP-U  [L402H24]  35.21 62.36 90 top
PL4302  MLVS0402M04-GP-U  [L402H24]  35.21 66.29 90 top
PL4303  MLVS0402M04-GP-U  [L402H24]  35.21 63.37 90 top
PL4701  IND-D36UH-19-GP  [L115100-2H158]  40.29 181.99 0 top
PL4702  IND-D36UH-19-GP  [L115100-2H158]  29.12 181.99 0 top
PL4802  IND-1D5UH-53-GP  [L686647H119]  39.78 156.34 0 top
PL4903  IND-3D3UH-116-GP-U  [L686647-127318H119]  128.56 10.67 270 top
PL4904  IND-2D2UH-122-GP  [L686647H119]  128.68 18.29 0 top
PL5001  IND-D68UH-36-GP  [L686647H119]  138.84 102.23 90 top
PL5003  IND-5D6UH-48-GP-U1  [L7066-1830-UH119]  42.71 61.47 0 bottom
PL5202  IND-2D2UH-122-GP  [L686647H119]  103.16 71.6 90 top
PL5401  IND-D36UH-19-GP  [L115100-2H158]  59.22 208.28 0 top
PQ4204  PDTC124EU-1-GP  [SOT323CBE2D2H44]  67.47 36.96 270 bottom
PQ4205  PDTA124EU-1-GP  [SOT323CBE2D2H44]  67.34 33.4 180 bottom
PQ4206  2N7002K-2-GP  [SOT23DGS2D4H44]  67.22 40.39 180 bottom
PQ4406  2N7002KDW-GP  [SOT-363H44]  73.44 56.13 0 bottom
PQ4408  2N7002K-2-GP  [SOT23DGS2D4H44]  71.69 63.98 0 top
PQ4409  MMBT3906-4-GP  [SOT23CBE2D4H44]  72.55 60.83 0 bottom
PQ5003  2N7002A-7-GP  [SOT23DGS2D4H48]  71.69 67.79 0 top
PQ5004  2N7002A-7-GP  [SOT23DGS2D4H48]  66.81 63.96 0 top
PQ5005  NTJD512NT1G-GP  [SOT-363H44]  48.55 38.99 0 top
PQ5006  2N7002KDW-GP  [SOT-363H44]  62.39 65.28 0 bottom
PR1  0R2J-2-GP  [R402H16]  121.19 72.52 180 bottom
PR2  -  [0R0402-PAD]  117 70.36 180 bottom
PR3  1KR2J-1-GP  [R402H16]  117.51 65.91 0 top
PR4  1KR2J-1-GP  [R402H16]  116.49 65.91 180 top
PR5  4K02R2F-GP  [R402H16]  118.14 72.52 180 bottom
PR6  1K91R2F-1-GP  [R402H16]  115.48 65.91 180 top
PR7  1KR2J-1-GP  [R402H16]  111.54 70.36 270 top
PR8  47KR2F-GP  [R402H16]  120.94 65.41 90 top
PR9  47KR2F-GP  [R402H16]  119.16 72.52 0 bottom
PR10  -  [0R0402-PAD]  116.49 67.94 0 top
PR11  0R0402-PAD-2-GP  [0R0402-PAD-1]  122.46 65.91 180 top
PR12  0R2J-2-GP  [R402H16]  122.97 67.44 90 top
PR13  8K06R2F-GP  [R402H16]  118.52 65.02 0 top
PR14  -  [0R0402-PAD]  115.35 67.94 0 top
PR15  1KR2J-1-GP  [R402H16]  111.54 70.36 270 bottom
PR16  1K21R2F-2-GP  [R402H16]  127.54 74.3 90 bottom
PR17  -  [0R0402-PAD]  114.84 70.36 90 top
PR18  -  [0R0402-PAD]  114.84 71.6 90 top
PR19  12KR2F-L-GP  [R402H16]  111.54 71.5 270 bottom
PR20  562R2F-GP  [R402H16]  128.3 69.72 90 top
PR21  1K87R2F-GP  [R402H16]  127.8 71.25 180 top
PR23  -  [0R0402-PAD]  114.84 72.64 90 top
PR24  0R0402-PAD-2-GP  [0R0402-PAD-1]  33.94 224.03 0 bottom
PR25  -  [0R0402-PAD]  114.84 73.79 90 top
PR26  1KR2J-1-GP  [R402H16]  111.54 73.79 270 top
PR28  -  [0R0402-PAD]  128.3 72.77 270 top
PR29  -  [0R0402-PAD]  128.3 73.79 270 top
PR30  -  [0R0402-PAD]  114.84 74.93 90 top
PR31  1KR2J-1-GP  [R402H16]  111.54 74.93 270 top
PR32  -  [0R0402-PAD]  114.84 76.07 90 top
PR33  1KR2J-1-GP  [R402H16]  111.54 76.07 270 top
PR34  82D5R2F-1-GP  [R402H16]  127.54 75.95 90 top
PR35  -  [0R0402-PAD]  114.84 77.22 90 top
PR36  1KR2J-1-GP  [R402H16]  111.54 77.22 270 top
PR37  -  [0R0402-PAD]  114.84 78.36 90 top
PR38  1KR2J-1-GP  [R402H16]  111.54 78.36 270 top
PR39  -  [0R0402-PAD]  114.84 79.5 90 top
PR40  1KR2J-1-GP  [R402H16]  111.54 79.5 270 top
PR41  11KR2F-L-GP  [R402H16]  127.54 75.44 90 bottom
PR42  2K61R2F-1-GP  [R402H16]  129.32 78.11 0 bottom
PR43  2D2R3-1-U-GP  [R603H22]  123.53 80.64 180 top
PR44  -  [0R0402-PAD]  117.25 80.64 180 top
PR45  3K65R3F-GP  [R603H22]  131.22 76.96 270 bottom
PR47  1R2F-GP  [R402H16]  131.48 74.17 180 bottom
PR51  NTC-10K-27-GP-U  [NTC-402H24-U]  121.83 115.19 270 top
PR57  10KR2F-2-GP  [R402H16]  101.25 62.61 270 bottom
PR60  NTC-470K-9-GP-U  [NTC-402H24-U]  129.07 94.36 180 top
PR62  10KR2F-2-GP  [R402H16]  101.25 60.58 90 top
PR77  10KR2F-2-GP  [R402H16]  67.72 81.28 180 top
PR78  6K98R2F-GP  [R402H16]  66.2 81.79 90 top
PR79  10R2F-L-GP  [R402H14]  64.3 80.77 270 top
PR83  10R2F-L-GP  [R402H14]  17.18 163.45 90 top
PR94  1KR2J-1-GP  [R402H16]  111.54 72.64 270 bottom
PR95  1R2F-GP  [R402H16]  128.3 78.11 180 bottom
PR96  1KR2J-1-GP  [R402H16]  111.54 73.79 270 bottom
PR97  1KR2J-1-GP  [R402H16]  111.54 74.93 270 bottom
PR98  0R0603-PAD-2-GP-U  [0R0603-PAD-1-U]  127.16 77.85 180 bottom
PR99  9K31R2F-GP  [R402H16]  127.54 78.36 270 top
PR100  1KR2J-1-GP  [R402H16]  111.54 76.07 270 bottom
PR101  -  [0R0402-PAD]  125.76 79.76 180 bottom
PR102  1KR2J-1-GP  [R402H16]  111.54 77.22 270 bottom
PR103  1KR2J-1-GP  [R402H16]  111.54 78.36 270 bottom
PR104  1KR2J-1-GP  [R402H16]  111.54 79.5 270 bottom
PR114  2D2R5J-1-GP  [R805H24]  120.94 97.66 0 top
PR190  10KR2J-3-GP  [R402H16]  106.97 6.99 0 top
PR225  10KR2J-3-GP  [R402H16]  72.42 79.38 270 top
PR4210  1KR2J-1-GP  [R402H16]  69.5 39.5 180 bottom
PR4214  3K3R6J-GP  [R1206H28]  67.22 30.23 270 bottom
PR4412  47KR2F-GP  [R402H16]  65.44 58.55 270 bottom
PR4413  100KR2F-L1-GP  [R402H16]  73.57 52.2 0 bottom
PR4425  3K3R2J-3-GP  [R402H16]  66.86 53.01 0 bottom
PR4426  3K3R2J-3-GP  [R402H16]  66.86 54.91 180 bottom
PR4427  100KR2J-1-GP  [R402H16]  65.95 60.83 90 bottom
PR4431  100KR2J-1-GP  [R402H16]  75.34 61.85 90 bottom
PR4433  1MR2J-1-GP  [R402H16]  75.34 60.83 270 bottom
PR4450  10KR2F-2-GP  [R402H16]  72.55 52.2 180 bottom
PR4451  680KR2F-GP  [R402H16]  75.34 59.82 270 bottom
PR4455  0R2J-2-GP  [R402H16]  75.47 56.64 0 bottom
PR4458  0R2J-2-GP  [R402H16]  74.2 65.41 270 bottom
PR4462  0R2J-2-GP  [R402H16]  73.06 58.42 270 bottom
PR4601  1KR2F-3-GP  [R402H16]  23.66 217.17 180 bottom
PR4602  2R2F-GP  [R402H16]  32.93 224.08 0 top
PR4603  10KR2F-2-GP  [R402H16]  24.67 209.17 180 bottom
PR4604  0R0402-PAD-2-GP  [0R0402-PAD-1]  23.78 224.03 0 bottom
PR4605  61K9R2F-GP  [R402H16]  27.85 224.03 180 bottom
PR4606  0R0402-PAD-2-GP  [0R0402-PAD-1]  24.8 224.03 0 bottom
PR4608  10KR2F-2-GP  [R402H16]  37.5 213.61 90 top
PR4609  27K4R2F-GP  [R402H16]  37.5 216.53 270 bottom
PR4610  54K9R2F-L-GP  [R402H16]  31.91 224.03 180 bottom
PR4611  100R2J-2-GP  [R402H14]  65.44 186.06 90 top
PR4612  10R2F-L-GP  [R402H14]  37.5 212.6 270 bottom
PR4613  NTC-100K-10-GP-U  [NTC-402H22-U]  51.21 196.34 180 top
PR4614  27K4R2F-GP  [R402H16]  27.34 218.82 90 top
PR4615  10KR2F-2-GP  [R402H16]  23.15 212.72 270 top
PR4616  1KR2F-3-GP  [R402H16]  36.36 222.66 270 top
PR4618  10R2F-L-GP  [R402H14]  23.15 211.71 90 bottom
PR4619  75KR2F-GP  [R402H16]  21.62 216.15 0 bottom
PR4620  165KR2F-GP  [R402H16]  23.15 215.65 90 top
PR4621  1KR2F-3-GP  [R402H16]  36.99 222.12 180 bottom
PR4622  49D9R2F-GP  [R402H16]  38.51 222.63 270 bottom
PR4623  8K2R2F-1-GP  [R402H16]  38.51 220.6 270 bottom
PR4624  10KR2F-2-GP  [R402H16]  28.86 224.03 180 bottom
PR4625  41K2R2F-GP  [R402H16]  38.26 213.61 270 bottom
PR4626  27K4R2F-GP  [R402H16]  23.15 215.65 90 bottom
PR4627  28K7R2F-GP  [R402H16]  33.05 217.04 270 top
PR4628  100R2J-2-GP  [R402H14]  65.44 187.2 90 top
PR4629  61K9R2F-GP  [R402H16]  34.96 220.73 180 top
PR4630  NTC-100K-10-GP-U  [NTC-402H22-U]  18.19 196.34 180 top
PR4631  0R2J-2-GP  [R402H16]  23.15 210.69 90 bottom
PR4632  10KR2F-2-GP  [R402H16]  29.88 224.03 180 bottom
PR4633  0R0402-PAD-2-GP  [0R0402-PAD-1]  37.5 211.58 270 bottom
PR4634  49D9R2F-GP  [R402H16]  23.15 221.62 90 bottom
PR4635  24KR2F-GP  [R402H16]  25.69 209.17 180 bottom
PR4636  1KR2F-3-GP  [R402H16]  23.15 220.6 90 bottom
PR4637  NTC-220K-GP-U  [NTC-402H22-U]  23.02 183.01 180 top
PR4638  1KR2F-3-GP  [R402H16]  36.99 218.06 180 bottom
PR4639  NTC-220K-GP-U  [NTC-402H22-U]  46.39 184.15 180 top
PR4640  75KR2F-GP  [R402H16]  39.02 218.06 0 bottom
PR4641  48D7KR2F-GP  [R402H16]  22.26 212.72 90 bottom
PR4642  0R0402-PAD-2-GP  [0R0402-PAD-1]  35.97 224.03 0 bottom
PR4643  100R2J-2-GP  [R402H14]  41.94 170.31 90 top
PR4644  300KR2F-GP  [R402H16]  37.5 216.53 270 top
PR4645  8K2R2F-1-GP  [R402H16]  22.26 219.58 90 bottom
PR4685  10R2F-L-GP  [R402H14]  72.17 222.88 0 bottom
PR4701  2D2R3-1-U-GP  [R603H22]  34.2 209.42 180 bottom
PR4702  2D2R6J-3-GP  [R1206H28]  42.96 191.9 180 top
PR4703  2D2R3-1-U-GP  [R603H22]  27.47 209.42 180 bottom
PR4704  2D2R6J-3-GP  [R1206H28]  26.45 191.9 180 top
PR4802  75KR2F-GP  [R402H16]  14.13 157.73 90 top
PR4803  11K8R2F-GP  [R402H16]  14.64 154.18 180 top
PR4805  10KR2J-3-GP  [R402H16]  15.53 159.38 0 top
PR4806  2D2R5J-1-GP  [R805H24]  30.39 156.34 270 top
PR4807  470KR2F-GP  [R402H16]  16.77 153.97 270 top
PR4812  2D2R3-1-U-GP  [R603H22]  23.53 160.15 90 top
PR4814  -  [0R0805-PAD]  25.31 163.07 90 top
PR4815  -  [0R0805-PAD]  25.31 165.1 90 top
PR4816  33KR2F-GP  [R402H16]  14.13 155.7 270 top
PR4901  100KR2J-1-GP  [R402H16]  114.46 10.16 180 top
PR4902  2D2R5J-1-GP  [R805H24]  110.4 6.22 180 top
PR4903  2D2R5J-1-GP  [R805H24]  110.9 17.65 180 top
PR4911  2D2R5J-1-GP  [R805H24]  127.08 9.55 90 bottom
PR4912  2D2R5J-1-GP  [R805H24]  127.16 20.47 90 bottom
PR4914  6K65R2F-GP  [R402H16]  105.95 10.03 180 top
PR4917  10KR2F-2-GP  [R402H16]  106.46 11.56 270 top
PR4918  56K2R2F-2-GP  [R402H16]  114.84 12.06 270 top
PR4919  68KR2F-GP  [R402H16]  106.46 12.06 90 bottom
PR4920  110KR2F-GP  [R402H16]  111.95 12.01 90 bottom
PR4921  15KR2F-GP  [R402H16]  105.95 14.1 180 top
PR4922  10KR2F-2-GP  [R402H16]  106.46 12.57 270 top
PR4924  249KR2F-GP  [R402H16]  106.46 11.05 90 bottom
PR4925  191KR2F-1-GP  [R402H16]  106.46 13.08 90 bottom
PR4927  -  [0R0805-PAD]  118.14 5.08 270 bottom
PR4929  -  [0R0805-PAD]  118.14 7.01 270 bottom
PR4930  -  [0R0805-PAD]  114.59 26.54 90 top
PR4931  -  [0R0805-PAD]  114.59 20.45 90 top
PR4932  -  [0R0805-PAD]  114.59 22.48 90 top
PR4933  -  [0R0805-PAD]  114.59 24.51 90 top
PR5002  5D1R2F-GP  [R402H16]  146.46 75.06 90 top
PR5003  10K5R2F-GP  [R402H16]  147.1 79.38 270 top
PR5004  -  [0R0603-PAD]  146.72 78.11 90 top
PR5005  10KR2F-2-GP  [R402H16]  145.98 72.62 180 top
PR5006  2D2R3-1-U-GP  [R603H22]  143.04 83.57 180 top
PR5007  620KR2F-GP  [R402H16]  144.94 73.53 180 top
PR5009  48D7KR2F-GP  [R402H16]  141.26 77.34 0 bottom
PR5018  -  [0R0805-PAD]  136.05 76.71 270 top
PR5019  -  [0R0805-PAD]  136.05 78.74 270 top
PR5020  -  [0R0805-PAD]  141.38 83.95 0 top
PR5021  -  [0R0805-PAD]  139.35 83.95 0 top
PR5023  40K2R2F-GP  [R402H16]  139.86 73.03 90 top
PR5032  -  [0R0805-PAD]  135.97 73.51 90 top
PR5034  2D2R5J-1-GP  [R805H24]  141.38 96.39 180 bottom
PR5201  20KR2F-L-GP  [R402H16]  101.25 62.61 90 top
PR5204  2D2R6J-3-GP  [R1206H28]  104.94 68.58 270 bottom
PR5205  2D2R3J-2-GP  [R603H22]  101.63 65.66 270 top
PR5206  10KR2F-2-GP  [R402H16]  111.41 64.39 270 top
PR5209  10KR2F-2-GP  [R402H16]  101.25 63.63 270 top
PR5223  10KR2F-2-GP  [R402H16]  101.25 63.63 90 bottom
PR5247  0R2J-2-GP  [R402H16]  40.55 20.07 180 top
PR5248  0R2J-2-GP  [R402H16]  39.53 20.07 180 top
PR5249  0R2J-2-GP  [R402H16]  43.59 20.07 180 top
PR5250  0R2J-2-GP  [R402H16]  42.58 20.07 180 top
PR5251  1KR2J-1-GP  [R402H16]  111.54 72.64 270 top
PR5261  0R2J-2-GP  [R402H16]  69.76 81.28 0 top
PR5268  33KR2F-GP  [R402H16]  64.8 51.31 180 bottom
PR5269  D01R3721F-GP-U  [R3720H40]  48.42 63.63 270 bottom
PR5270  309KR2F-GP  [R402H16]  65.82 59.69 90 bottom
PR5272  49K9R2F-L-GP  [R402H16]  52.48 40.77 270 top
PR5273  100KR2J-1-GP  [R402H16]  69.35 66.6 180 top
PR5274  -  [0R0402-PAD]  65.82 51.31 180 bottom
PR5275  100KR2J-1-GP  [R402H16]  54.01 40.77 0 top
PR5276  D01R3721F-GP-U  [R3720H40]  55.28 46.86 180 top
PR5277  7D5R2F-GP  [R402H16]  61.5 51.31 180 bottom
PR5278  100KR2J-1-GP  [R402H16]  63.79 51.31 0 bottom
PR5279  1D5R2F-GP  [R402H16]  56.14 54.84 90 bottom
PR5281  100KR2J-1-GP  [R402H16]  69.35 64.62 0 top
PR5282  10KR2F-2-GP  [R402H16]  52.48 39.75 270 top
PR5283  10R2F-L-GP  [R402H14]  60.49 51.31 180 bottom
PR5284  20R5F-1GP  [R805H24]  55.53 58.93 90 top
PR5285  470KR2J-2-GP  [R402H16]  42.68 72.36 270 top
PR5286  10KR2F-2-GP  [R402H16]  62.64 51.31 180 bottom
PR5287  3D3MR2J-GP  [R402H16]  59.98 61.34 270 bottom
PR5288  -  [0R0402-PAD]  65.39 55.5 270 bottom
PR5289  100KR2J-1-GP  [R402H16]  70.52 61.09 180 top
PR5290  -  [0R0805-PAD]  22.89 148.72 0 top
PR5291  -  [0R0603-PAD]  33.69 144.78 270 top
PR5292  10KR2F-2-GP  [R402H16]  30.26 141.22 180 top
PR5293  8K87R2F-2-GP  [R402H16]  30.26 143.26 180 top
PR5294  2D2R5J-1-GP  [R805H24]  19.72 146.18 90 top
PR5295  10KR2F-2-GP  [R402H16]  19.85 144.65 90 top
PR5296  -  [0R0603-PAD]  33.69 143.38 270 top
PR5297  100KR2J-1-GP  [R402H16]  71.53 61.09 180 top
PR5298  120KR2F-L-GP  [R402H16]  69.25 62.48 180 top
PR5401  2D2R6J-3-GP  [R1206H28]  53.5 217.81 0 bottom
PR5402  34KR2F-GP  [R402H16]  78.52 218.69 0 top
PR5404  2D2R3-1-U-GP  [R603H22]  71.66 212.47 90 bottom
PR5407  49D9R2F-GP  [R402H16]  83.85 223.9 0 bottom
PR5408  10KR2F-2-GP  [R402H16]  71.15 222.88 0 bottom
PR5409  39KR2F-GP  [R402H16]  73.19 222.88 0 bottom
PR5410  100R2J-2-GP  [R402H14]  73.31 193.29 180 bottom
PR5411  27K4R2F-GP  [R402H16]  83.73 209.55 0 bottom
PR5412  24KR2F-GP  [R402H16]  76.11 216.92 90 top
PR5413  1KR2F-3-GP  [R402H16]  83.35 222.38 90 bottom
PR5414  NTC-220K-GP-U  [NTC-402H22-U]  65.31 209.3 0 top
PR5415  8K2R2F-1-GP  [R402H16]  81.44 224.41 90 bottom
PR5416  100R2J-2-GP  [R402H14]  72.3 193.29 180 bottom
PR5417  1KR2F-3-GP  [R402H16]  79.66 223.39 90 bottom
PR5418  2R2F-GP  [R402H16]  85.25 213.23 90 bottom
PR5419  10KR2F-2-GP  [R402H16]  76.11 217.93 90 top
PR5420  0R2J-2-GP  [R402H16]  86.14 219.71 270 bottom
PR5421  61K9R2F-GP  [R402H16]  80.55 218.69 180 top
PR5422  0R2J-2-GP  [R402H16]  86.14 218.69 270 bottom
PR5423  NTC-100K-20-GP  [NTC-402H24-U]  51.6 208.28 270 bottom
PR5424  1KR2F-3-GP  [R402H16]  81.69 209.55 0 bottom
PR5425  75KR2F-GP  [R402H16]  77.12 222.88 180 bottom
PR5426  165KR2F-GP  [R402H16]  76.11 222.88 180 bottom
PR5428  36KR2F-GP  [R402H16]  78.14 222.88 0 bottom
PR5429  10KR2F-2-GP  [R402H16]  73.82 218.57 0 top
PR5431  10KR2J-3-GP  [R402H16]  89.57 14.86 90 top
PR5463  10KR2F-2-GP  [R402H16]  85.25 215.52 90 bottom
PR5464  0R2J-2-GP  [R402H16]  80.68 209.55 180 bottom
PR5466  0R2J-2-GP  [R402H16]  85.25 216.53 270 bottom
PR5467  102KR2F-GP  [R402H16]  64.04 61.34 90 bottom
PR5468  110KR2F-GP  [R402H16]  64.04 62.36 270 bottom
PR5469  56K2R2F-2-GP  [R402H16]  62.52 61.85 180 bottom
PR5470  107KR2F-GP  [R402H16]  61.5 60.83 0 bottom
PR5471  0R2J-2-GP  [R402H16]  110.65 92.96 180 bottom
PR5472  4K99R2F-L-GP  [R402H16]  152.31 204.6 90 top
PR5473  6K49R2F-1-GP  [R402H16]  151.04 203.07 180 top
PR5475  2D2R3-1-U-GP  [R603H22]  164.5 206.63 270 top
PR5476  0R2J-2-GP  [R402H16]  167.29 91.44 0 bottom
PR8519  3K3R2J-3-GP  [R402H16]  95.16 58.8 270 bottom
PR8520  3K3R2J-3-GP  [R402H16]  95.16 59.82 270 bottom
PR8521  0R2J-2-GP  [R402H16]  85.5 55.12 90 bottom
PSWD1  JOWLE-CON2-5-GP  [A2541WV0-1EX2PA-6T]  153.2 114.43 270 top
PT1  E820U2D5VM-14-GP  [ECAP-100D6D3H355]  109.43 100.46 0 top
PT2  SE47U25VM-14-GP  [SE361416H237]  127.16 86.74 0 top
PT3  E820U2D5VM-14-GP  [ECAP-100D6D3H355]  109.46 116.2 0 top
PT4  E820U2D5VM-14-GP  [ECAP-100D6D3H355]  109.46 108.33 0 top
PT4701  SE47U25VM-13-GP  [SE361414H241]  47.91 202.06 180 top
PT4702  E820U2D5VM-6-GP  [ECAP-100D6D3H375]  50.71 173.99 0 top
PT4703  E820U2D5VM-6-GP  [ECAP-100D6D3H375]  36.86 170.81 0 top
PT4704  E820U2D5VM-6-GP  [ECAP-100D6D3H375]  28.99 170.81 0 top
PT4708  E820U2D5VM-6-GP  [ECAP-100D6D3H375]  58.58 181.74 0 top
PT4709  E820U2D5VM-6-GP  [ECAP-100D6D3H375]  50.71 181.86 0 top
PT4712  SE47U25VM-13-GP  [SE361414H241]  21.5 202.06 180 top
PT4801  E820U2D5VM-6-GP  [ECAP-100D6D3H375]  48.17 152.53 0 top
PT4901  SE47U25VM-13-GP  [SE361414H241]  120.3 22.86 0 top
PT4902  SE220U6D3VM-8GP  [SE331721H237]  136.94 9.78 180 top
PT4903  SE220U6D3VM-8GP  [SE331721H237]  136.94 19.18 0 top
PT5007  E820U2D5VM-14-GP  [ECAP-100D6D3H355]  138.08 110.62 270 top
PT5401  E820U2D5VM-6-GP  [ECAP-100D6D3H375]  55.79 189.1 0 top
PT5402  E820U2D5VM-6-GP  [ECAP-100D6D3H375]  63.66 196.98 0 top
PT5403  E820U2D5VM-6-GP  [ECAP-100D6D3H375]  55.79 196.98 0 top
PT5405  SE47U25VM-13-GP  [SE361414H241]  43.11 218.44 180 top
PU1  AON6552-GP  [PPAK-8P-5262H40]  125.26 95 180 top
PU2  AON6552-GP  [PPAK-8P-5262H40]  125.26 95 0 bottom
PU3  AON6508-GP  [PPAK-8P-5262H40]  116.62 97.03 0 top
PU4  AP2138N-1D5TRG1-GP  [SOT23-2D8-312H58]  158.15 120.14 0 top
PU5  APL5337KAI-TRG-GP  [SOIC8-G3530H63]  157.51 204.98 90 bottom
PU7  APL5912-KAC-TRG-GP  [SOIC8-G3530H63]  67.22 77.22 270 top
PU4403  AON7410-GP  [PPAK-8P-3232H36]  40.55 57.15 180 top
PU4405  AON7410-GP  [PPAK-8P-3232H36]  44.99 58.67 0 top
PU4601  NCP81128MNTXG-GP-U  [LFCSP52J6-G4D8H40]  30.39 217.81 180 bottom
PU4702  AON6520-GP  [PPAK-8P-5262H40]  22 194.18 0 top
PU4703  AON6510-GP  [PPAK-8P-5262H40]  30.89 192.41 0 bottom
PU4704  AON6510-GP  [PPAK-8P-5262H40]  30.89 192.41 180 top
PU4705  AON6510-GP  [PPAK-8P-5262H40]  38.51 192.41 180 top
PU4706  AON6510-GP  [PPAK-8P-5262H40]  38.51 192.41 0 bottom
PU4801  AON6510-GP  [PPAK-8P-5262H40]  32.16 152.02 270 top
PU4802  AON6520-GP  [PPAK-8P-5262H40]  30.39 160.66 90 top
PU4803  RT8237CZQW-2-GP  [DFN10G3-G265175H32]  18.7 156.84 90 top
PU4901  RT8243BZQW-GP  [QFN20-G1D75H32]  110.65 12.01 90 top
PU4902  AON7410-GP  [PPAK-8P-3232H36]  124.11 6.35 270 bottom
PU4903  AON7410-GP  [PPAK-8P-3232H36]  125.64 12.83 90 bottom
PU4904  AON7410-GP  [PPAK-8P-3232H36]  124.21 23.75 270 bottom
PU4905  AON7410-GP  [PPAK-8P-3232H36]  125.64 17.22 90 bottom
PU5001  RT8207MZQW-GP-U  [QFN20-G1D75H32]  142.02 78.36 90 top
PU5006  AON6520-GP  [PPAK-8P-5262H40]  136.56 92.84 180 top
PU5007  AON6510-GP  [PPAK-8P-5262H40]  143.16 94.61 0 top
PU5201  RT6220AGQUF-GP  [QFN16J3H24]  106.59 64.52 180 top
PU5202  AON6508-GP  [PPAK-8P-5262H40]  116.62 97.03 180 bottom
PU5204  AO4407AL-GP  [SOIC8H69]  58.2 42.04 270 top
PU5205  AO4407AL-GP  [SOIC8H69]  40.8 68.96 90 top
PU5206  APL5930KAI-TRG-1-GP  [SOIC8-G3530H63]  25.81 143.89 90 top
PU5207  AON6520-GP  [PPAK-8P-5262H40]  47.4 194.18 0 top
PU5401  AON6520-GP  [PPAK-8P-5262H40]  51.6 212.09 270 bottom
PU5402  AON6510-GP  [PPAK-8P-5262H40]  64.68 218.82 0 bottom
PU5403  AON6510-GP  [PPAK-8P-5262H40]  57.95 218.82 0 bottom
PU5407  NCP81128MNTXG-GP-U  [LFCSP52J6-G4D8H40]  78.77 215.77 90 bottom
PWRCN1  ACES-CON10-30-GP  [51530-01041-W01]  26.75 22.5 270 top
Q1  2N7002A-7-GP  [SOT23DGS2D4H48]  37.96 111.61 90 bottom
Q3  2N7002A-7-GP  [SOT23DGS2D4H48]  128.94 211.96 270 bottom
Q4  2N7002KDW-1-GP  [SOT-363H44]  36.15 75.59 270 bottom
Q5  2N7002A-7-GP  [SOT23DGS2D4H48]  37.96 115.21 90 bottom
Q7  2N7002KDW-1-GP  [SOT-363H44]  32.57 75.59 270 bottom
Q10  MMBT3904-4-GP  [SOT23CBE2D4H44]  34.07 118.11 180 bottom
Q12  MMBT3904DW-GP  [SOT-363H44]  41.82 76.53 270 bottom
Q13  MMBT3904DW-GP  [SOT-363H44]  46.26 75.9 90 bottom
Q14  SSM3K329R-1-GP  [SOT23DGS2D4H35]  18.45 165.86 0 top
Q18  2N7002KDW-1-GP  [SOT-363H44]  56.29 141.6 270 top
Q22  MMBT3904-4-GP  [SOT23CBE2D4H44]  44.99 28.7 90 top
Q24  AZ5125-02S-R7G-GP  [SOT23-2D4-312H46]  165.18 70 180 bottom
Q28  2N7002-11-GP  [SOT23DGS2D4H44]  164.63 66.98 0 top
Q31  MMBT3904-4-GP  [SOT23CBE2D4H44]  161.07 66.98 0 top
Q36  MMBT3904DW-GP  [SOT-363H44]  32.55 7.87 90 top
Q37  2N7002KDW-GP  [SOT-363H44]  134.4 57.78 180 top
Q38  MMBT3904-4-GP  [SOT23CBE2D4H44]  29.5 22.73 0 bottom
Q43  AO4468L-GP  [SOIC8H69]  88.93 28.96 0 top
Q44  AO3413L-GP  [SOT23DGS2D8H50]  41.94 6.99 180 bottom
Q45  MMBT3904-4-GP  [SOT23CBE2D4H44]  51.16 36.14 180 bottom
Q46  AZ5125-02S-R7G-GP  [SOT23-2D4-312H46]  84.11 42.16 270 top
Q47  2N7002A-7-GP  [SOT23DGS2D4H48]  57.77 36.14 0 bottom
Q48  MMBT3904-4-GP  [SOT23CBE2D4H44]  101.63 92.46 90 top
Q50  PMBS3904-1-GP  [SOT-23-10H44]  93.76 222.88 0 top
Q51  2N7002A-7-GP  [SOT23DGS2D4H48]  19.34 223.14 90 bottom
Q52  MMBT3904-4-GP  [SOT23CBE2D4H44]  15.53 223.14 90 bottom
Q56  2N7002A-7-GP  [SOT23DGS2D4H48]  160.38 86.33 180 bottom
Q57  AZ5125-02S-R7G-GP  [SOT23-2D4-312H46]  165.51 76.58 270 bottom
Q63  MMBT3904DW-GP  [SOT-363H44]  141.64 30.68 270 top
Q64  2N7002A-7-GP  [SOT23DGS2D4H48]  143.49 34.09 270 top
Q65  2N7002KDW-1-GP  [SOT-363H44]  37.75 140.34 0 top
Q68  2N7002A-7-GP  [SOT23DGS2D4H48]  25.94 23.75 0 bottom
Q76  2N7002A-7-GP  [SOT23DGS2D4H48]  166.15 91.31 270 top
Q77  AO3413L-GP  [SOT23DGS2D8H50]  160.43 91.57 0 top
Q78  2N7002H-GP  [SOT23DGS2D4H44]  64.68 134.87 0 top
Q79  2N7002H-GP  [SOT23DGS2D4H44]  69.38 136.27 270 top
Q95  2N7002KDW-1-GP  [SOT-363H44]  53.5 71.63 90 top
Q97  2N7002KDW-1-GP  [SOT-363H44]  109.76 95 270 top
Q100  MMBT3904-4-GP  [SOT23CBE2D4H44]  42.96 6.99 0 top
Q101  MMBT3904-4-GP  [SOT23CBE2D4H44]  47.53 6.99 0 top
Q102  MMBT3904-4-GP  [SOT23CBE2D4H44]  46.52 6.99 0 bottom
Q103  2N7002A-7-GP  [SOT23DGS2D4H48]  42.63 117.91 180 top
Q104  2N7002A-7-GP  [SOT23DGS2D4H48]  91.98 17.65 90 bottom
Q105  2N7002A-7-GP  [SOT23DGS2D4H48]  94.14 17.27 270 top
Q107  2N7002A-7-GP  [SOT23DGS2D4H48]  135.8 50.04 270 top
Q123  2N7002KDW-1-GP  [SOT-363H44]  103.41 96.39 0 top
Q128  MMBT3904-4-GP  [SOT23CBE2D4H44]  128.94 215.65 270 bottom
Q1207  MMBT3904-4-GP  [SOT23CBE2D4H44]  107.98 159.26 90 bottom
Q1208  MMBT3904-4-GP  [SOT23CBE2D4H44]  73.19 135.25 270 top
Q1209  2N7002-11-GP  [SOT23DGS2D4H44]  77 135.25 270 top
Q1210  AO3413L-GP  [SOT23DGS2D8H50]  98.59 222.88 180 top
Q1211  AO3413L-GP  [SOT23DGS2D8H50]  125 205.87 0 bottom
Q1212  2N7002A-7-GP  [SOT23DGS2D4H48]  28.99 13.46 0 bottom
Q1213  MMBT3904-4-GP  [SOT23CBE2D4H44]  30.51 27.43 270 bottom
Q1214  MMBT3904-4-GP  [SOT23CBE2D4H44]  26.07 32.13 90 bottom
Q1217  2N7002KDW-1-GP  [SOT-363H44]  94.01 21.46 90 top
Q1226  2N7002KDW-1-GP  [SOT-363H44]  153.91 46.74 0 bottom
Q1227  2N7002H-GP  [SOT23DGS2D4H44]  162.85 41.02 180 top
Q1229  2N7002K-2-GP  [SOT23DGS2D4H44]  103.41 223.01 270 top
Q1240  2N7002-11-GP  [SOT23DGS2D4H44]  88.05 210.08 180 bottom
Q1241  MMBT3904-4-GP  [SOT23CBE2D4H44]  71.03 208.91 0 bottom
Q1243  2N7002-11-GP  [SOT23DGS2D4H44]  48.42 159.38 0 top
Q1244  2N7002-11-GP  [SOT23DGS2D4H44]  48.42 163.19 0 top
Q1245  2N7002-11-GP  [SOT23DGS2D4H44]  48.42 168.02 180 top
Q1246  2N7002H-GP  [SOT23DGS2D4H44]  59.98 135.51 270 top
Q1247  2N7002-11-GP  [SOT23DGS2D4H44]  51.98 168.02 180 top
Q1248  2N7002-11-GP  [SOT23DGS2D4H44]  51.98 163.19 180 top
Q1249  2N7002A-7-GP  [SOT23DGS2D4H48]  126.53 29.21 0 top
Q1250  AO4286-GP  [SOIC8H69]  43.14 45.75 270 bottom
Q4701  2N7002KDW-1-GP  [SOT-363H44]  151.16 210.06 270 top
Q6701  2N7002KDW-GP  [SOT-363H44]  82.08 64.54 0 top
Q6702  2N7002KDW-1-GP  [SOT-363H44]  101.51 124.46 90 top
Q6703  DMN2016LHAB-7-GP  [DFN6F2030-G1619H26]  156.12 210.95 270 bottom
Q6704  DMN2016LHAB-7-GP  [DFN6F2030-G1619H26]  156.12 215.26 270 bottom
Q6705  MMBT3904DW-GP  [SOT-363H44]  88.68 119 270 top
Q9646  2N7002KDW-GP  [SOT-363H44]  25.69 13.08 0 bottom
Q9647  AO3413L-GP  [SOT23DGS2D8H50]  42.07 114.43 0 bottom
Q9648  2N7002A-7-GP  [SOT23DGS2D4H48]  86.01 57.53 90 bottom
Q9649  AO3413L-GP  [SOT23DGS2D8H50]  88.3 51.69 0 bottom
Q9650  2N7002A-7-GP  [SOT23DGS2D4H48]  42.07 119.38 0 bottom
R1  100KR2J-1-GP  [R402H16]  101 224.03 180 top
R5  10R2F-L-GP  [R402H14]  43.11 38.1 270 top
R8  330R3J-L-GP  [R603H22]  38.51 109.22 90 bottom
R10  8K2R2J-3-GP  [R402H16]  126.53 211.2 0 bottom
R12  10KR2J-3-GP  [R402H16]  157.26 195.33 90 top
R13  39K2R2F-L-GP  [R402H16]  125.51 211.2 180 bottom
R14  0R2J-2-GP  [R402H16]  122.08 220.47 270 top
R15  0R0402-PAD-2-GP  [0R0402-PAD-1]  131.48 212.6 0 bottom
R19  1MR2J-1-GP  [R402H16]  34.7 109.68 0 bottom
R20  470KR2F-GP  [R402H16]  38.77 119.38 270 bottom
R22  0R0402-PAD-2-GP  [0R0402-PAD-1]  104.17 215.14 270 top
R23  0R0402-PAD-2-GP  [0R0402-PAD-1]  104.17 216.15 270 top
R24  0R3J-0-U-GP  [R603H22]  158.53 194.44 180 bottom
R26  100KR2J-1-GP  [R402H16]  36.86 119.38 90 bottom
R27  D33R6F-GP  [R1206H26]  49.13 48.87 270 bottom
R30  100KR2J-1-GP  [R402H16]  36.86 118.36 90 bottom
R31  0R2J-2-GP  [R402H16]  23.02 139.57 180 top
R32  4K7R2J-2-GP  [R402H16]  39.94 86.49 0 bottom
R33  100KR2J-1-GP  [R402H16]  34.83 115.7 270 bottom
R35  0R0402-PAD-2-GP  [0R0402-PAD-1]  37.12 86.49 0 bottom
R37  0R1206-PAD-1-GP  [0R1206-PAD-1]  34.45 35.38 0 top
R39  22R2J-2-GP  [R402H16]  34.83 114.68 270 bottom
R41  10KR2J-3-GP  [R402H16]  33.82 113.67 90 bottom
R42  10KR2J-3-GP  [R402H16]  33.31 115.19 0 bottom
R43  0R0402-PAD-2-GP  [0R0402-PAD-1]  50.96 71.3 180 top
R45  100R2F-L1-GP-U  [R402H14]  34.96 31.88 180 bottom
R46  4K7R2J-2-GP  [R402H16]  35.09 86.49 0 bottom
R47  4K7R2J-2-GP  [R402H16]  31.53 85.09 270 bottom
R51  0R0402-PAD-2-GP  [0R0402-PAD-1]  30.89 41.15 90 top
R53  0R0402-PAD-2-GP  [0R0402-PAD-1]  30.89 40.13 90 top
R54  4K7R2J-2-GP  [R402H16]  56.8 72.14 0 top
R56  0R0402-PAD-2-GP  [0R0402-PAD-1]  31.53 37.08 90 top
R57  4K7R2J-2-GP  [R402H16]  39.12 74.32 270 top
R58  4K7R2J-2-GP  [R402H16]  31.53 84.07 270 bottom
R59  0R0402-PAD-2-GP  [0R0402-PAD-1]  31.53 36.07 90 top
R60  0R0402-PAD-2-GP  [0R0402-PAD-1]  38.13 72.39 90 top
R61  1KR2F-3-GP  [R402H16]  37.65 32.03 0 top
R65  0R5J-5-GP  [R805H24]  44.38 41.91 90 bottom
R68  100R2F-L1-GP-U  [R402H14]  11.46 217.68 0 top
R69  4K7R2J-2-GP  [R402H16]  52.74 73.66 270 top
R71  2K2R2J-2-GP  [R402H16]  12.61 217.68 0 top
R73  20KR2J-L2-GP  [R402H16]  15.91 207.01 180 top
R74  0R0402-PAD-2-GP  [0R0402-PAD-1]  16.92 207.01 180 top
R76  8K2R2F-1-GP  [R402H16]  15.91 208.91 180 top
R77  0R2J-2-GP  [R402H16]  101.25 61.59 90 bottom
R78  1KR2F-3-GP  [R402H16]  137.7 191.9 0 bottom
R80  4K7R2J-2-GP  [R402H16]  15.91 210.82 0 top
R81  0R2J-2-GP  [R402H16]  87.03 186.56 0 top
R82  10KR2F-2-GP  [R402H16]  33.94 31.88 180 bottom
R93  1KR2J-1-GP  [R402H16]  85 194.69 0 top
R99  0R0402-PAD-2-GP  [0R0402-PAD-1]  154.34 182.63 90 bottom
R101  -  [0R0805-PAD]  8.29 210.44 180 bottom
R107  150R2F-1-GP  [R402H16]  70.14 186.56 180 top
R110  0R2J-2-GP  [R402H16]  19.08 163.45 90 top
R111  100R2F-L1-GP-U  [R402H14]  165.64 128.91 90 top
R113  1MR3F-GP  [R603H22]  64.93 172.97 0 top
R115  1KR2F-3-GP  [R402H16]  95.28 166.37 90 bottom
R118  100KR2J-1-GP  [R402H16]  76.36 132.97 90 top
R119  100KR2J-1-GP  [R402H16]  78.27 132.97 90 top
R120  1KR2F-3-GP  [R402H16]  145.7 152.91 180 bottom
R121  39D2R2F-L-GP  [R402H16]  94.14 161.04 270 bottom
R122  1KR2F-3-GP  [R402H16]  147.61 150.88 180 bottom
R123  22R2J-2-GP  [R402H16]  79.28 143.51 180 top
R124  10KR2J-3-GP  [R402H16]  71.66 138.56 270 top
R125  0R2J-2-GP  [R402H16]  18.96 159.13 0 bottom
R131  0R2J-2-GP  [R402H16]  46.21 35.48 90 top
R132  100KR2J-1-GP  [R402H16]  45.22 32.36 270 top
R133  4K7R2J-2-GP  [R402H16]  46.21 34.44 270 top
R134  10KR2J-3-GP  [R402H16]  46.74 31.93 180 top
R135  4K7R2J-2-GP  [R402H16]  45.12 26.29 90 top
R137  10KR2J-3-GP  [R402H16]  60.74 156.08 180 top
R138  10KR2J-3-GP  [R402H16]  42.58 29.72 0 top
R139  4K7R2J-2-GP  [R402H16]  42.58 27.69 180 top
R143  1KR2J-1-GP  [R402H16]  45.12 25.27 270 top
